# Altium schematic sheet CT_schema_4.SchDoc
size 405 x 311 mm
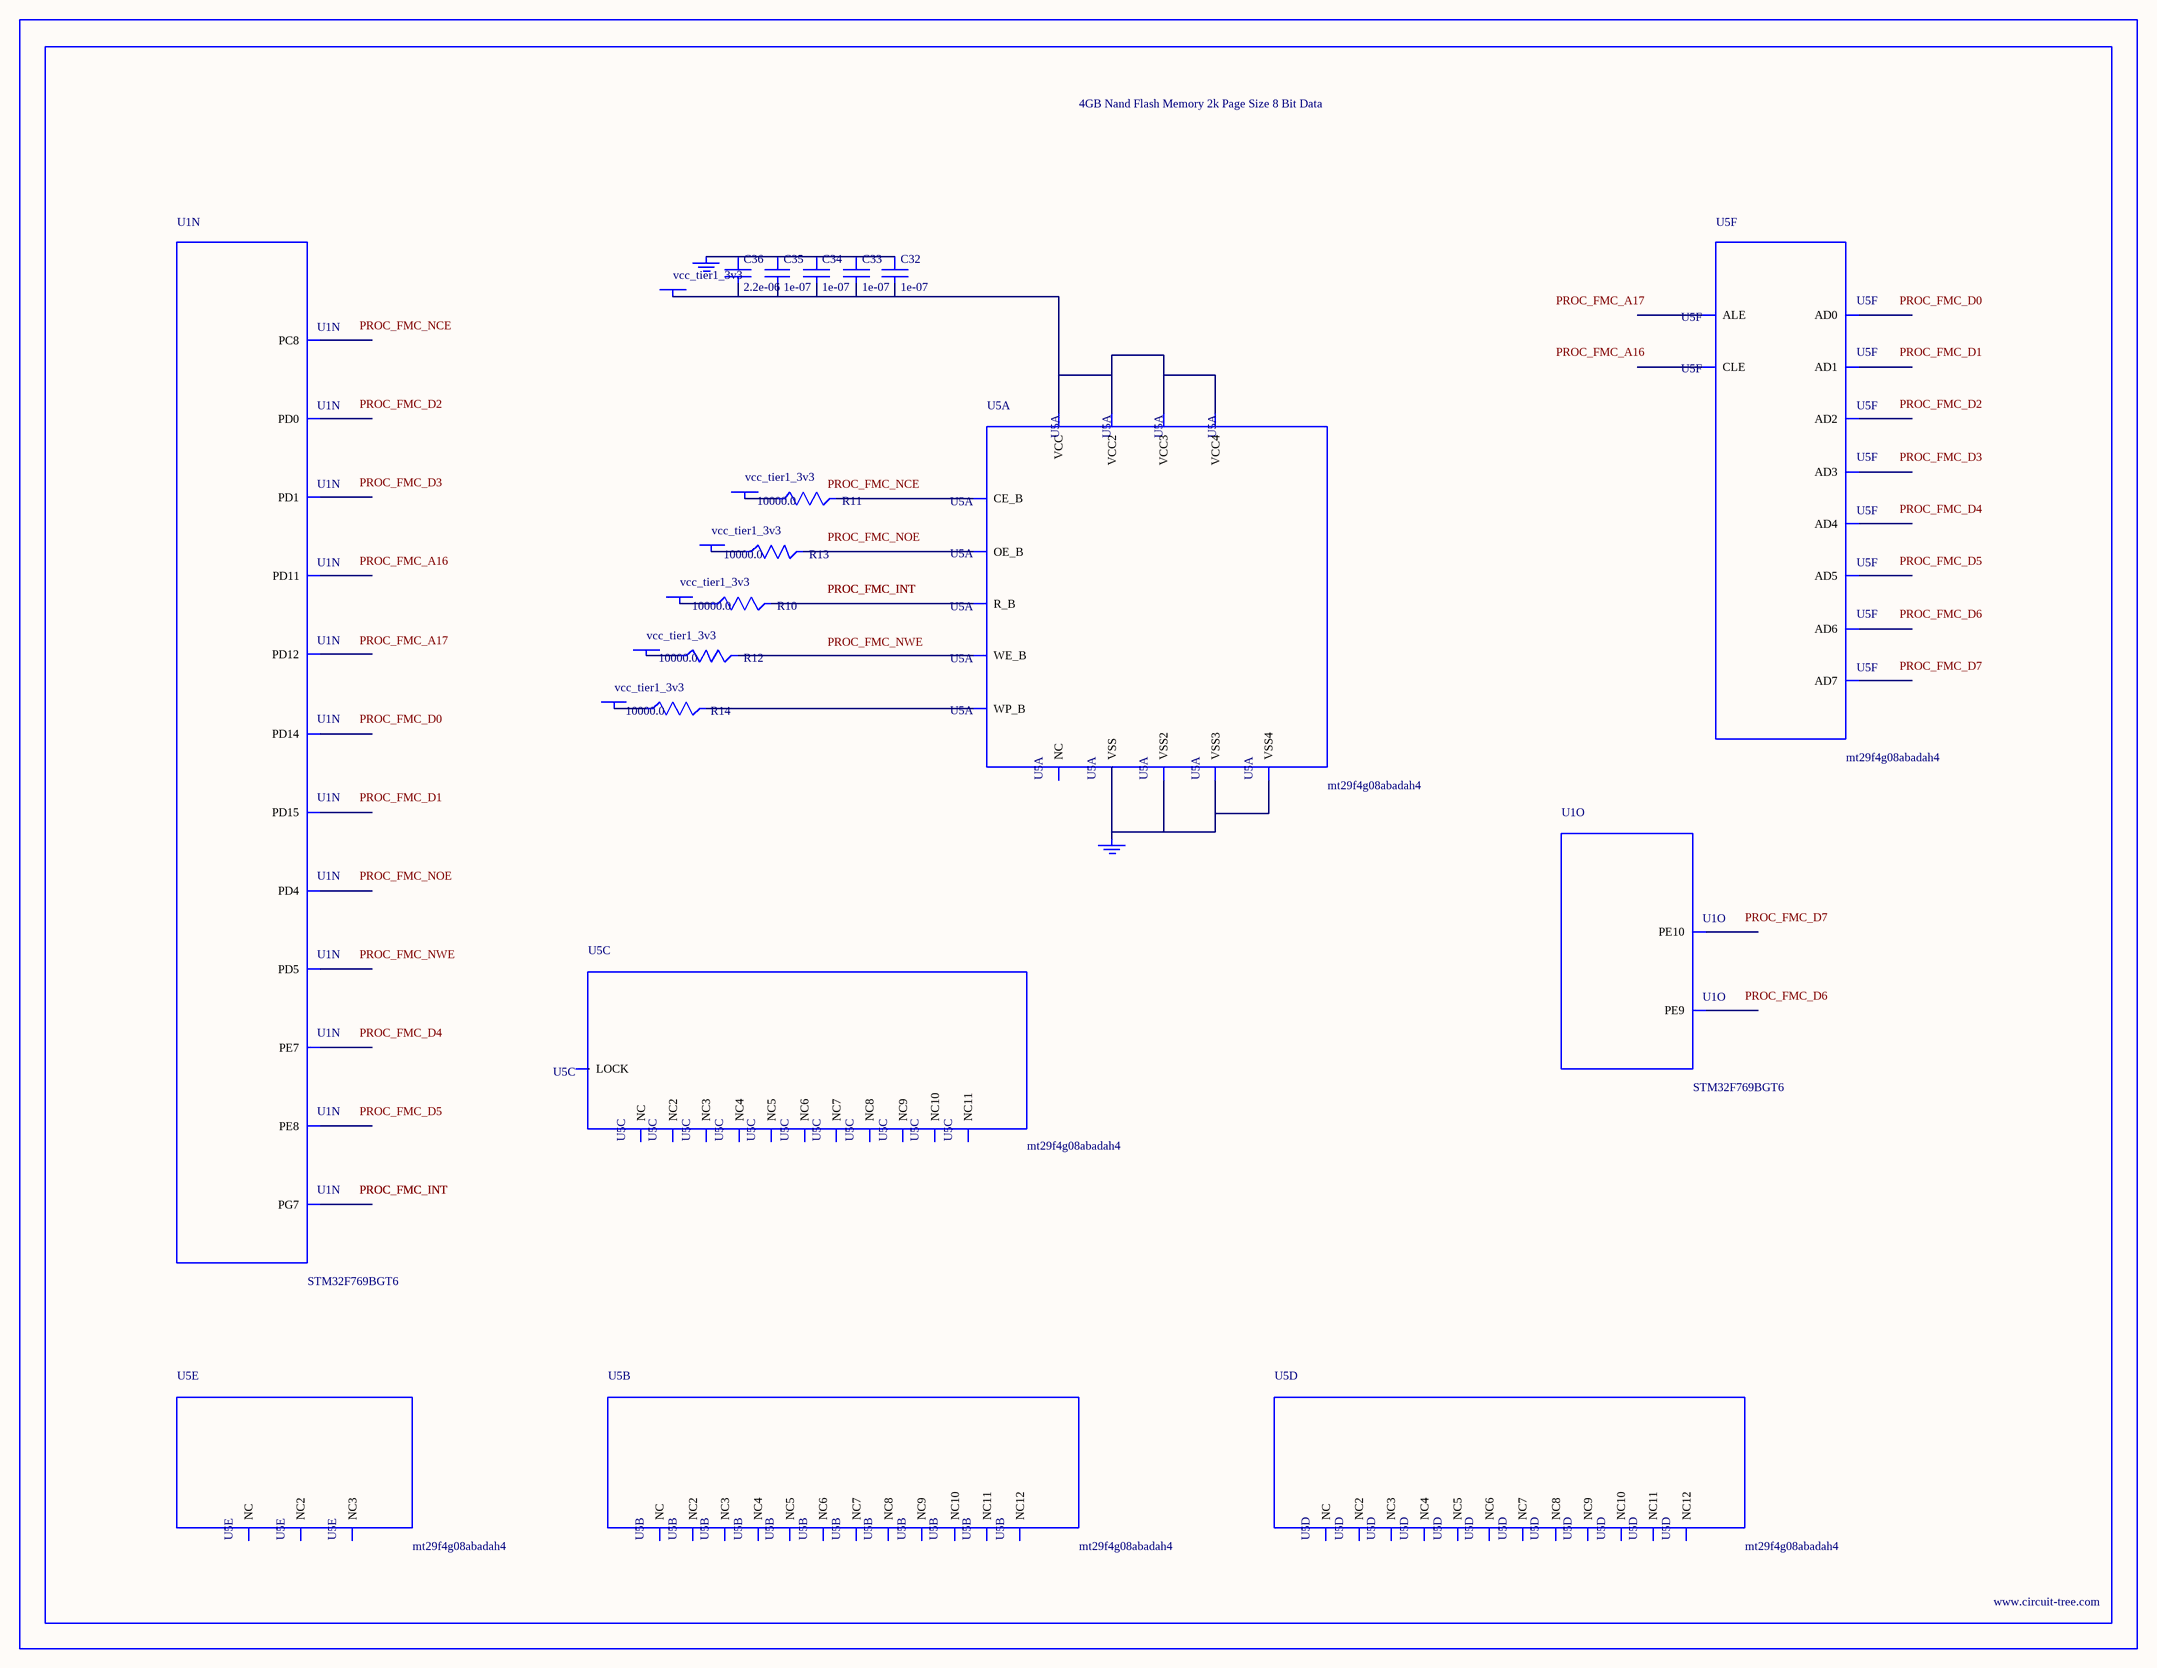
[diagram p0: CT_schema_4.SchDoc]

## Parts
BORDER3  (no value)
C32  1e-07  [C0402]
C33  1e-07  [C0402]
C34  1e-07  [C0402]
C35  1e-07  [C0402]
C36  2.2e-06  [C0603]
GND_INSTANCE_3_0  (no value)
GND_INSTANCE_3_1  (no value)
POWER_INSTANCE_3_0  vcc_tier1_3v3
POWER_INSTANCE_3_1  vcc_tier1_3v3
POWER_INSTANCE_3_2  vcc_tier1_3v3
POWER_INSTANCE_3_3  vcc_tier1_3v3
POWER_INSTANCE_3_4  vcc_tier1_3v3
POWER_INSTANCE_3_5  vcc_tier1_3v3
R10  10000.0  [R0603]
R11  10000.0  [R0603]
R12  10000.0  [R0603]
R13  10000.0  [R0603]
R14  10000.0  [R0603]
U1  STM32F769BGT6  [LQFP208]  (parts N,O of 17)
U5  mt29f4g08abadah4  [VFBGA-63]  (parts A,B,C,D,E,F of 6)

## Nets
NetC32_1: C32.1 C33.1 C34.1 C35.1 C36.1 GND_INSTANCE_3_0.0(GND)
NetC32_2: C32.2 C33.2 C34.2 C35.2 C36.2 POWER_INSTANCE_3_0.0(PWR) U5.D3(VCC) U5.G4(VCC2) U5.H8(VCC3) U5.J6(VCC4)
NetGND_INSTANCE_3_1_0: GND_INSTANCE_3_1.0(GND) U5.C5(VSS) U5.F7(VSS2) U5.K3(VSS3) U5.K8(VSS4)
NetPOWER_INSTANCE_3_1_0: POWER_INSTANCE_3_1.0(PWR) R10.1
NetPOWER_INSTANCE_3_2_0: POWER_INSTANCE_3_2.0(PWR) R11.1
NetPOWER_INSTANCE_3_3_0: POWER_INSTANCE_3_3.0(PWR) R12.1
NetPOWER_INSTANCE_3_4_0: POWER_INSTANCE_3_4.0(PWR) R13.1
NetPOWER_INSTANCE_3_5_0: POWER_INSTANCE_3_5.0(PWR) R14.1
NetR10_2: R10.2 U5.C8(R_B)
NetR11_2: R11.2 U5.C6(CE_B)
NetR12_2: R12.2 U5.C7(WE_B)
NetR13_2: R13.2 U5.D4(OE_B)
NetR14_2: R14.2 U5.C3(WP_B)

Not connected (* = marked no-connect by the designer): U1 79(PE7) 80(PE8) 81(PE9) 84(PE10) 111(PD11) 112(PD12) 116(PD14) 117(PD15) 134(PG7) 140(PC8) 164(PD0) 165(PD1) 168(PD4) 169(PD5); U5 A1(NC) A2(NC3) A9(NC4) A10(NC2) B1(NC5) B9(NC7) B10(NC6) C4(ALE) D5(CLE) D6(NC8) D7(NC9) D8(NC10) E3(NC11) E4(NC12) E5(NC) E6(NC2) E7(NC3) E8(NC4) F3(NC5) F4(NC6) F5(NC7) F6(NC8) F8(NC9) G3(NC) G5(LOCK) G6(NC10) G7(NC11) G8(NC) H3(NC2) H4(AD0) H5(NC3) H6(NC4) H7(NC5) J3(NC6) J4(AD1) J5(NC7) J7(AD5) J8(AD7) K4(AD2) K5(AD3) K6(AD4) K7(AD6) L1(NC8) L2(NC10) L9(NC11) L10(NC9) M1(NC12) M2(NC2) M9(NC3) M10(NC)

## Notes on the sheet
- Labels drawn without touching a wire or pin: PROC_FMC_A16, PROC_FMC_A17, PROC_FMC_D0, PROC_FMC_D1, PROC_FMC_D2, PROC_FMC_D3, PROC_FMC_D4, PROC_FMC_D5, PROC_FMC_D6, PROC_FMC_D7, PROC_FMC_NCE, PROC_FMC_NOE, PROC_FMC_NWE

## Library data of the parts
BORDER3 = BORDER_PAGE3
C32-C35 = C0402C104K3RACTU
C36 = C0603C225K8RACTU
GND_INSTANCE_3_0 GND_INSTANCE_3_1 = GND
POWER_INSTANCE_3_0-POWER_INSTANCE_3_5 = PWR
R10-R14 = RC0603JR-0710KL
